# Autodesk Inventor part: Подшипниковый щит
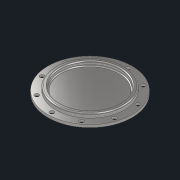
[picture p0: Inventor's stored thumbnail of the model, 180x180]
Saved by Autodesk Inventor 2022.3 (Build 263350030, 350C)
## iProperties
Created: 2022-08
Part Number: Подшипниковый щит
Material: Сталь 40ХНМА
Document SubType Name: Modeling
Designer: Карташов
Density: 7.85 g/cm^3
Appearance: С умеренной полировкой
Author: Карташов
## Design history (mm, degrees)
sketch "Эскиз1"
  geometry: L1 (0, 0)-(0, 34.001); L2 (50, -5)-(80, -5); L3 (80, -5)-(80, 0); L4 (80, 0)-(65, 0); L5 (65, 0)-(65, 6); L6 (63, 8)-(59, 8); L7 (57, 6)-(57, 2); L8 (55, 0)-(0, 0); L9 (50, -5)-(48, -7); L10 (48, -7)-(0, -7); L11 (0, -7)-(0, 0); A1 r 2 centre (55, 2) between (55, 0) and (57, 2); A2 r 2 centre (63, 6) between (65, 6) and (63, 8); A3 r 2 centre (59, 6) between (59, 8) and (57, 6); 4 further points
  constraints: 22 end point, 6 point on circle, 6 tangent, 5 horizontal, 4 point on line, 3 centre point, 3 vertical, 2 midpoint, 2 perpendicular
  dimensions: "d0" = 130 diameter of L5 point (0, 17); "d1" = 160 diameter of L3 L1; "d4" = 5 distance of L2.end L3.end; "d5" = 8 distance between parallel lines of L8 L6; "d6" = 8 distance of point (65, 8) point (57, 8); "d7" = 2 radius of A1; "d21" = 2 horizontal distance of L2.start L9.end; "d22" = 2 horizontal distance of L2.start L9.end; "d23" = 100 diameter of L2.start L1; "d24" = 2 radius of A2; "d25" = 2 radius of A3 (derived); "d26" = 15 distance from line of point (61, 8) L10
revolve "Вращение1" sketch "Эскиз1" stored, may be unused: angle "d9" = 90 deg
sketch "Эскиз2"
  geometry: C1 r 65 at (0, 0) reference; C2 r 80 at (0, 0) reference; 2 further points
  constraints: 1 vertical alignment
  dimensions: "d10" = 72.5 distance of point (0, 0) point (0, -72.5)
  node "Спроецированная петля1"
sketch "Эскиз3"
  geometry: 2 further points
hole "Отверстие1" sketch "Эскиз3" at (0, 72.5) diameter "d11" = 8; stored, may be unused: countersink angle "d15" = 90 deg, drill point angle "d17" = 0 deg; dims "d12" = 6, "d13" = 13, "d14" = 1, "d16" = 22.5
pattern_circular "Круговой массив1" dims angle "d19" = 360 deg
node "Твердое тело1"
